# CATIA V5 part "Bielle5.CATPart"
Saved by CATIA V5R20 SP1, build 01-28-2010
Part number: Bielle5
Bounding box of the stored display mesh (mm): x 5 to 10, y -16.033 to 5.966, z 117.615 to 158
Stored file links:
  J:\ACHTUNG2\Bielle5.CATPart
  J:\ACHTUNG2\cmilovidof.CATProduct
  J:\ACHTUNG\IAO non optimisé fini et qui marche à rendre\Bielle5.CATPart
  J:\ACHTUNG2\skl_Bielle4.CATPart
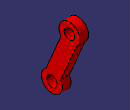
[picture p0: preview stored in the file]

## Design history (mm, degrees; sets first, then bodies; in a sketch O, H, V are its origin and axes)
External parameters (linked from other documents)
  External.diam_roue = 64 mm
Set1
  Plane1: linked copy from another document
  Line1 "Axe_Bielle5Equerre7": linked copy from another document
  Line2 "Axe_Bielle5Levier1": linked copy from another document
  Line3: linked copy from another document
Body1 (main body)
  Sketch1 on Plane1, origin (5, 0, 0), H (0, 1, 0), V (0, 0, 1)
    point P2 (-10.0334, 123.5885)
    construction circle A1 centre (0, 152) radius 6
    point P3 (-4.8034, 148.4045)
    construction circle A2 centre (-10.0334, 123.5885) radius 6
    point P4 (-13.2669, 128.6426)
    point P5 (-4.8034, 148.4045)
    point P6 (-4.9688, 126.8057)
    point P7 (-4.9688, 126.8057)
    point P8 (-13.2669, 128.6426)
    arc A3 centre (0, 152) radius 6 from (3.8505, 147.3985) to (-4.8034, 148.4045) ccw
    line L1 (3.8505, 147.3985) -> (-4.9688, 126.8057)
    line L2 (-4.8034, 148.4045) -> (-13.2669, 128.6426)
    arc A4 centre (-10.0334, 123.5885) radius 6 from (-13.2669, 128.6426) to (-4.9688, 126.8057) ccw
    reference projected point E1 (0, 152) from Line2
    circle A5 centre (0, 152) radius 3
    circle A6 centre (-10.0334, 123.5885) radius 3
    reference projected point E2 (-10.0334, 123.5885) from Line3
    radius A3 = 6 {= External.diam_roue *6/64}
    radius A4 = 6 {= External.diam_roue *6/64}
    radius A5 = 3 {= 3*External.diam_roue /64}
    radius A6 = 3 {= 3*External.diam_roue /64}
    coincidence: P3 A1, P4 A2, P5 A1, P6 A2, P7 A2, P3 P5, P4 P8, P6 P7, A3 A1, P2 E2
    parallelism: L2 L1
    concentricity: E1 A1, A6 A2, A4 A2
    tangency: A5 L2
  Pad1: profile Sketch1, direction (1, 0, 0), length 5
